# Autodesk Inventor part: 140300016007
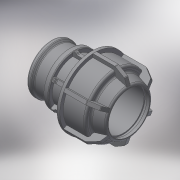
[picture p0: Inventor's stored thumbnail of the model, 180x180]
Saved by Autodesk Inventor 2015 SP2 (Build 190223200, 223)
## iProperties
Created: 2017-08
Part Number: 140300016007
Material: Generic
Description: PLASSON L.14 FEMALE ADAPTOR (SILVER) 16-3/4"
Document SubType Name: Modeling
Designer: KIM
Density: 1 g/cm^3
Appearance: Default
Author: KIM
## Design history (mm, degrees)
derived "140300.ipt"
feature "Solid1::140300.ipt"
tag "TaggingFeature1"
body "Solid1"
other parameters: "d1" = 16, "d2" = 56, "d4" = 15 deg, "d5" = 36.96, "d6" = 12.1968, "d9" = 24.117, "d10" = 39, "d11" = 31.3521, "d12" = 28.9404, "d13" = 33.7638, "d14" = 19, "d16" = 16.32, "d17" = 2.8, "d18" = 79, "d19" = 5.7, "d20" = 135 deg, "d21" = 5.7, "d22" = 28.9404, "d23" = 14.4, "d24" = 2.8, "d25" = 35.1, "d26" = 29.25, "d27" = 2.8, "d28" = 135 deg, "d29" = 1.68, "d31" = 0.8, "d44" = 0.32, "d45" = 0.48, "d46" = 150 deg, "d49" = 1.95, "d50" = 0, "d51" = 0.39, "d52" = 0.78, "d53" = 45 deg, "d55" = 7.404, "d56" = 1.95, "d57" = 0, "d58" = 0.48, "d61" = 360 deg, "d_" = 16, "G_" = 24.117, "E_" = 39, "H_" = 79, "l_" = 56, "l_2" = 19, "d54" = 18.51
